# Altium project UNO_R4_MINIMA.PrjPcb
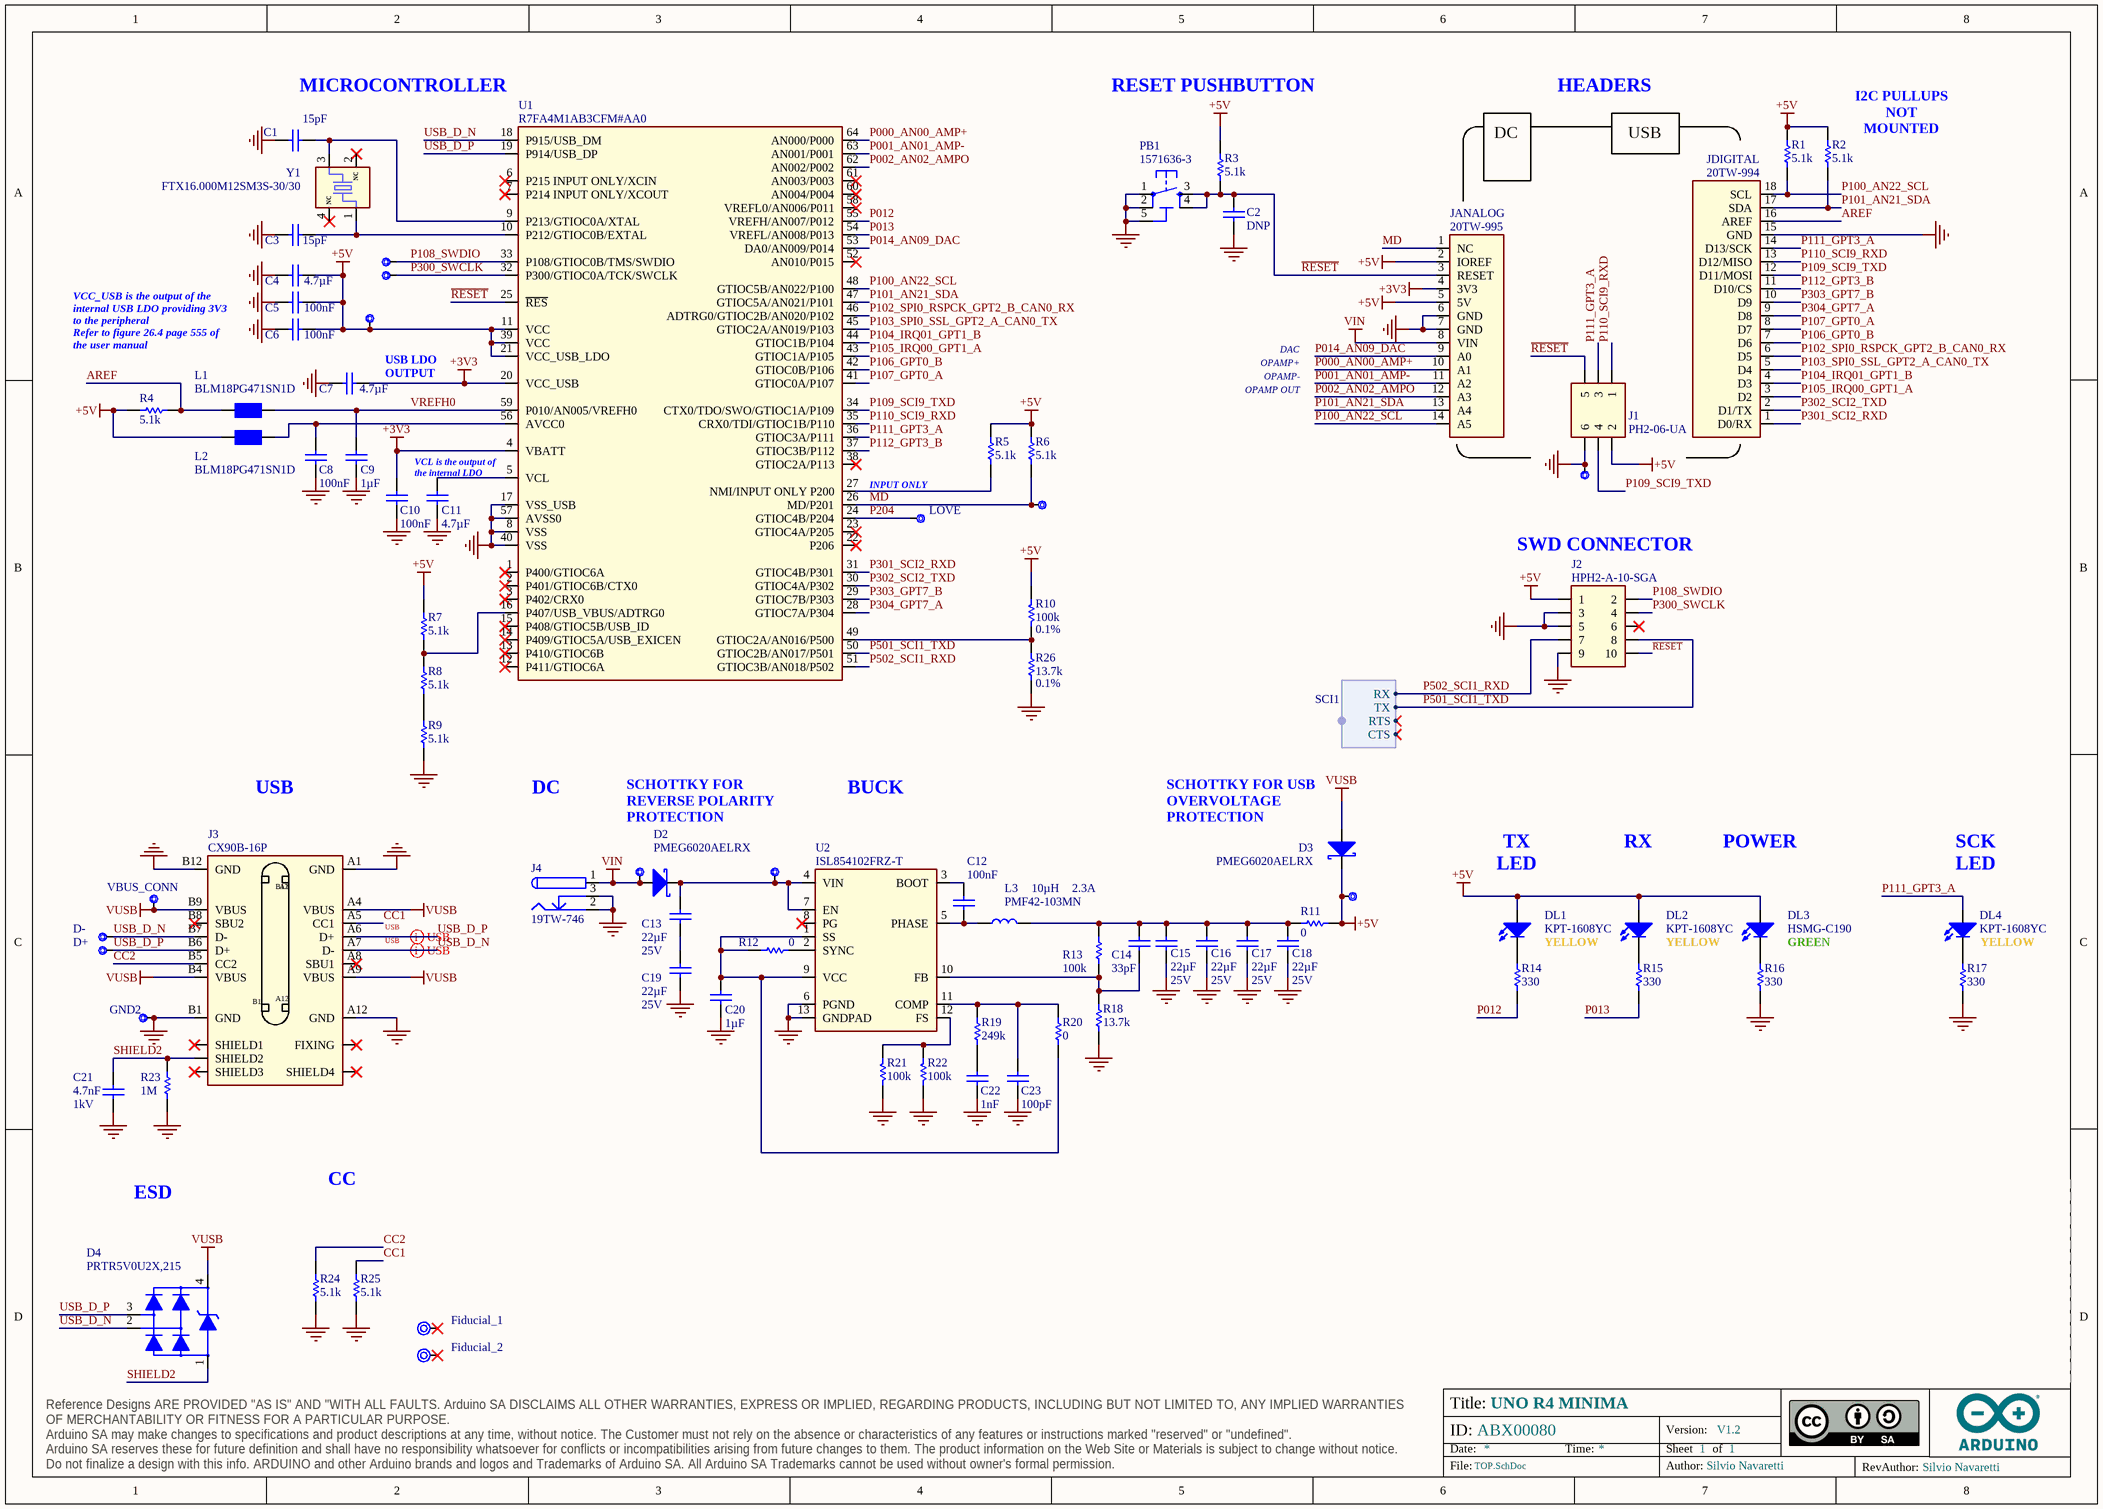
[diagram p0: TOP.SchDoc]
ASSEMBLY_BGA: _; ASSEMBLY_PRESSFIT: _; ASSEMBLY_SMD: X; ASSEMBLY_THT: X; BOARD_INFO_AUTHOR: Silvio Navaretti; BOARD_INFO_Er: _; BOARD_INFO_FLEX: _; BOARD_INFO_FR4: X; BOARD_INFO_FR4_HTG: _; BOARD_INFO_IPC1: _; BOARD_INFO_IPC2: _; BOARD_INFO_IPC3: _; BOARD_INFO_IPC_NA: X; BOARD_INFO_NUMBER_OF_LAYERS: 2; BOARD_INFO_PCB_SIZE: 68.58mm x 53.34mm; BOARD_INFO_POLYMIDE: _; BOARD_INFO_RIGID: X; BOARD_INFO_RIGID/FLEX: _; BOARD_INFO_TBD: _; BOARD_INFO_THICKNESS: 1.6mm; DRILLS_BLIND: _; DRILLS_BURIED: _; DRILLS_COPPER_FILLING: _; DRILLS_FULL: X; DRILLS_LASER: _; DRILLS_PRESSFIT: _; DRILLS_RESIN_FILLING: _; DRILLS_SLOT: _; DRILLS_SOLDER_FILLING: X; FINISH_ADJUSTMENTS: _; FINISH_EDGE_PLATING: _; FINISH_ENIG: _; FINISH_HAL: _; FINISH_HAL_LF: X; FINISH_NI/AU: _; FINISH_SILK_BOTTOM: X; FINISH_SILK_COLOR: WHITE; FINISH_SILK_TOP: X; FINISH_SN/PB: _; FINISH_SOLDERMASK_BOTTOM: X; FINISH_SOLDERMASK_COLOR: BLUE; FINISH_SOLDERMASK_PEELABLE_BOTTOM: _; FINISH_SOLDERMASK_PEELABLE_COLOR: _; FINISH_SOLDERMASK_PEELABLE_TOP: _; FINISH_SOLDERMASK_TOP: X; FINISH_TABS: _; FINISH_TBD: _; INSULATION_MIN_INNER: 0.15mm; INSULATION_MIN_OUTER: 0.15mm; PANEL_MILLING: X; PANEL_NOT_REQUESTED: _; PANEL_NUMBER_OF_FIGURES: 10; PANEL_PROVIDED: X; PANEL_REQUESTED: _; PANEL_SCORING: X; PANEL_SIZE: 284.7mm x 157.16mm; PANEL_TABS: _; SKU: ABX00080; TRACK_MIN_WIDTH_INNER: 0.15mm; TRACK_MIN_WIDTH_OUTER: 0.15mm; Version: V1.2; VIA_1: _; VIA_1_HOLE_MM: _; VIA_1_PAD_MM: _; VIA_2: _; VIA_2_HOLE_MM: _; VIA_2_PAD_MM: _; VIA_3: _; VIA_3_HOLE_MM: _; VIA_3_PAD_MM: _; VIA_4: _; VIA_4_HOLE_MM: _; VIA_4_PAD_MM: _; VIA_5: _; VIA_5_HOLE_MM: _; VIA_5_PAD_MM: _; VIA_THROUGH: X; VIA_THROUGH_HOLE_MM: 0.3; VIA_THROUGH_PAD_MM: 0.6
1 sheet, 84 parts. Net scope: hierarchical (ports join the sheet entries above them; power ports are global).
Board file: PCB.PcbDoc

## Sheet TOP.SchDoc: UNO R4 MINIMA
size A3; Author: Silvio Navaretti; CompanyName: ARDUINO SRL; DrawnBy: Silvio Navaretti; Engineer: Silvio Navaretti; Organization: ARDUINO SRL; Address1: Via Agostino Da Montefeltro 2 Torino TO, Italy; DocumentNumber: ABX00080; Revision: V1.0; SheetNumber: 1; SheetTotal: 1; RevAuthor: Silvio Navaretti

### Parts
1  CMP-018-0004-A.4  [TP-0.8MM]  (value not drawn)  (no BOM)
BUCK_IN_TOP1  CMP-018-0004-A.4  [TP-0.8MM]  (value not drawn)  (no BOM)
C1  value 15pF  [CAP-0402]  (hidden comment: C0402C150J5GACTU)
C2  DNP  [CAP-0402]
C3  value 15pF  [CAP-0402]  (hidden comment: C0402C150J5GACTU)
C4  value 4.7µF  [CAP-0603]  (hidden comment: GRM188R61C475KAAJD)
C5  value 100nF  [CAP-0402]  (hidden comment: GRM155R61H104KE19D)
C6  value 100nF  [CAP-0402]  (hidden comment: GRM155R61H104KE19D)
C7  value 4.7µF  [CAP-0603]  (hidden comment: GRM188R61C475KAAJD)
C8  value 100nF  [CAP-0402]  (hidden comment: GRM155R61H104KE19D)
C9  value 1µF  [CAP-0402]  (hidden comment: CL05A105KP5NNNC)
C10  value 100nF  [CAP-0402]  (hidden comment: GRM155R61H104KE19D)
C11  value 4.7µF  [CAP-0603]  (hidden comment: GRM188R61C475KAAJD)
C12  value 100nF  [CAP-0402]  (hidden comment: GRM155R61H104KE19D)
C13  value 22µF  Voltage: 25V  [CAP-0805]  (hidden comment: CL21A226MAQNNNE)
C14  value 33pF  [CAP-0402]  (hidden comment: GRM1555C1H330JA01D)
C15  value 22µF  Voltage: 25V  [CAP-0805]  (hidden comment: CL21A226MAQNNNE)
C16  value 22µF  Voltage: 25V  [CAP-0805]  (hidden comment: CL21A226MAQNNNE)
C17  value 22µF  Voltage: 25V  [CAP-0805]  (hidden comment: CL21A226MAQNNNE)
C18  value 22µF  Voltage: 25V  [CAP-0805]  (hidden comment: CL21A226MAQNNNE)
C19  value 22µF  Voltage: 25V  [CAP-0805]  (hidden comment: CL21A226MAQNNNE)
C20  value 1µF  [CAP-0402]  (hidden comment: CL05A105KP5NNNC)
C21  value 4.7nF  Voltage: 1kV  [CAP-0805]  (hidden comment: FV21X472K102ECG)
C22  value 1nF  [CAP-0402]  (hidden comment: GRM155R71H102KA01D)
C23  value 100pF  [CAP-0402]  (hidden comment: CC0402JRNPO9BN101)
D2  PMEG6020AELRX  [SOD123-1]
D3  PMEG6020AELRX  [SOD123-1]
D4  PRTR5V0U2X,215  [SOT190P230X110-4N]
D+  CMP-018-0005-A.3  [TP-1.00MM]  (value not drawn)  (no BOM)
D-  CMP-018-0005-A.3  [TP-1.00MM]  (value not drawn)  (no BOM)
DL1  KPT-1608YC  [LEDC1608X80N-AK]
DL2  KPT-1608YC  [LEDC1608X80N-AK]
DL3  HSMG-C190  [LEDC1608X80N-AK]
DL4  KPT-1608YC  [LEDC1608X80N-AK]
Fiducial_1  Fiducial mark 1mm with 2mm solder  [Fiducial mark 1mm with circle-Footprint-1]  (value not drawn)  (no BOM)
Fiducial_2  Fiducial mark 1mm with 2mm solder  [Fiducial mark 1mm with circle-Footprint-1]  (value not drawn)  (no BOM)
GND1  CMP-018-0005-A.3  [TP-1.00MM]  (value not drawn)  (no BOM)
GND2  CMP-018-0005-A.3  [TP-1.00MM]  (value not drawn)  (no BOM)
J1  PH2-06-UA  [2X03]
J2  HPH2-A-10-SGA  [PINHEAD_2X05_127]
J3  CX90B-16P  [CX90B-16P-Footprint-1]
J4  19TW-746  [POWERSUPPLY_DC-21MM]
JANALOG  20TW-995  [1X14-CUSTOM]
JDIGITAL  20TW-994  [1X18-CUSTOM]
L1  BLM18PG471SN1D  [L-0603]
L2  BLM18PG471SN1D  [L-0603]
L3  PMF42-103MN  Max DC Current: 2.3A  Inductance: 10µH  [PMF42]
LOVE  CMP-018-0005-A.3  [TP-1.00MM]  (value not drawn)  (no BOM)
MD  CMP-018-0005-A.3  [TP-1.00MM]  (value not drawn)  (no BOM)
PB1  1571636-3  [TS42]
R1  value 5.1k  [RES-0603]  (hidden comment: CR0603AFX-5101EAS)
R2  value 5.1k  [RES-0603]  (hidden comment: CR0603AFX-5101EAS)
R3  value 5.1k  [RES-0402]  (hidden comment: RC0402FR-075K1L)
R4  value 5.1k  [RES-0402]  (hidden comment: RC0402FR-075K1L)
R5  value 5.1k  [RES-0402]  (hidden comment: RC0402FR-075K1L)
R6  value 5.1k  [RES-0402]  (hidden comment: RC0402FR-075K1L)
R7  value 5.1k  [RES-0402]  (hidden comment: RC0402FR-075K1L)
R8  value 5.1k  [RES-0402]  (hidden comment: RC0402FR-075K1L)
R9  value 5.1k  [RES-0402]  (hidden comment: RC0402FR-075K1L)
R10  value 100k  Tolerance: 0.1%  [RES-0402]  (hidden comment: WF04H1003BT)
R11  value 0  [RES-0402]  (hidden comment: CRCW04020000Z0EDC)
R12  value 0  [RES-0402]  (hidden comment: CRCW04020000Z0EDC)
R13  value 100k  [RES-0402]  (hidden comment: CRCW0402100KFKEDC)
R14  value 330  [RES-0402]  (hidden comment: CRCW0402330RJNED)
R15  value 330  [RES-0402]  (hidden comment: CRCW0402330RJNED)
R16  value 330  [RES-0402]  (hidden comment: CRCW0402330RJNED)
R17  value 330  [RES-0402]  (hidden comment: CRCW0402330RJNED)
R18  value 13.7k  [RES-0402]  (hidden comment: RC0402FR-0713K7L)
R19  value 249k  [RES-0402]  (hidden comment: AC0402FR-07249KL)
R20  value 0  [RES-0402]  (hidden comment: CRCW04020000Z0EDC)
R21  value 100k  [RES-0402]  (hidden comment: CRCW0402100KFKEDC)
R22  value 100k  [RES-0402]  (hidden comment: CRCW0402100KFKEDC)
R23  value 1M  [RES-0402]  (hidden comment: CRCW04021M00FKED)
R24  value 5.1k  [RES-0402]  (hidden comment: RC0402FR-075K1L)
R25  value 5.1k  [RES-0402]  (hidden comment: RC0402FR-075K1L)
R26  value 13.7k  Tolerance: 0.1%  [RES-0402]  (hidden comment: WF04H1372BTL)
SWCLK1  CMP-018-0005-A.3  [TP-1.00MM]  (value not drawn)  (no BOM)
SWDIO1  CMP-018-0005-A.3  [TP-1.00MM]  (value not drawn)  (no BOM)
U1  R7FA4M1AB3CFM#AA0  [CQFP50P1200X1200X170-64L]
U2  ISL854102FRZ-T  [QFN0P300X400X100_HS-13L]
VBUS_CONN  CMP-018-0005-A.3  [TP-1.00MM]  (value not drawn)  (no BOM)
VCC1  CMP-018-0005-A.3  [TP-1.00MM]  (value not drawn)  (no BOM)
VIN_TOP1  CMP-018-0004-A.4  [TP-0.8MM]  (value not drawn)  (no BOM)
Y1  FTX16.000M12SM3S-30/30  [CRYSTAL_3.2x2.5mm_16MHz]

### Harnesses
SCI1: RX, TX, RTS, CTS

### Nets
+3V3: C7.2 C10.2 JANALOG.4(3V3) U1.4(VBATT) U1.20(VCC_USB)
+5V: 1.X C4.2 C5.2 C6.2 D3.C DL1.A DL2.A DL3.A J1.2 J2.1 JANALOG.2(IOREF) JANALOG.5(5V) L2.1 R1.2 R2.2 R3.2 R4.2 R5.1 R6.1 R7.2 R10.2 R11.2 U1.11(VCC) U1.21(VCC_USB_LDO) U1.39(VCC) VCC1.X
GND: C1.2 C2.2 C3.2 C4.1 C5.1 C6.1 C7.1 C8.1 C9.2 C10.1 C11.1 C15.1 C16.1 C17.1 C18.1 C19.1 C20.2 C21.1 C22.1 C23.1 GND1.X GND2.X J1.6 J2.3 J2.5 J2.9 J3.A1(GND) J3.A12(GND) J3.B1(GND) J3.B12(GND) J4.2 J4.3 JANALOG.6(GND) JANALOG.7(GND) JDIGITAL.15(GND) PB1.1 PB1.2 PB1.5(5-GND) R9.1 R16.1 R17.1 R18.1 R21.1 R22.1 R23.1 R24.1 R25.1 R26.1 U1.8(VSS) U1.17(VSS_USB) U1.40(VSS) U1.57(AVSS0) U2.6(PGND) U2.13(GNDPAD)
VIN: D2.A J4.1 JANALOG.8(VIN) VIN_TOP1.X
VUSB: D3.A D4.4 J3.A4(VBUS) J3.A9(VBUS) J3.B4(VBUS) J3.B9(VBUS) VBUS_CONN.X
AREF: JDIGITAL.16(AREF) L1.1 R4.1  [project net AREF_1]
CC1: J3.A5(CC1) R25.2  [project net CC1_1]
CC2: J3.B5(CC2) R24.2  [project net CC2_1]
MD: JANALOG.1(NC) MD.X R6.2 U1.26(MD/P201)  [project net MD_1]
P000_AN00_AMP+: JANALOG.10(A1) U1.64(AN000/P000)  [project net P000_AN00_AMP+_1]
P001_AN01_AMP-: JANALOG.11(A2) U1.63(AN001/P001)  [project net P001_AN01_AMP-_1]
P002_AN02_AMPO: JANALOG.12(A3) U1.62(AN002/P002)  [project net P002_AN02_AMPO_1]
P012: R14.1 U1.55(VREFH/AN007/P012)  [project net P012_1]
P013: R15.1 U1.54(VREFL/AN008/P013)  [project net P013_1]
P014_AN09_DAC: JANALOG.9(A0) U1.53(DA0/AN009/P014)  [project net P014_AN09_DAC_1]
P100_AN22_SCL: JANALOG.14(A5) JDIGITAL.18(SCL) R1.1 U1.48(GTIOC5B/AN022/P100)  [project net P100_AN22_SCL_1]
P101_AN21_SDA: JANALOG.13(A4) JDIGITAL.17(SDA) R2.1 U1.47(GTIOC5A/AN021/P101)  [project net P101_AN21_SDA_1]
P102_SPI0_RSPCK_GPT2_B_CAN0_RX: JDIGITAL.6(D5) U1.46(ADTRG0/GTIOC2B/AN020/P102)  [project net P102_SPI0_RSPCK_GPT2_B_CAN0_RX_1]
P103_SPI0_SSL_GPT2_A_CAN0_TX: JDIGITAL.5(D4) U1.45(GTIOC2A/AN019/P103)  [project net P103_SPI0_SSL_GPT2_A_CAN0_TX_1]
P104_IRQ01_GPT1_B: JDIGITAL.4(D3) U1.44(GTIOC1B/P104)  [project net P104_IRQ01_GPT1_B_1]
P105_IRQ00_GPT1_A: JDIGITAL.3(D2) U1.43(GTIOC1A/P105)  [project net P105_IRQ00_GPT1_A_1]
P106_GPT0_B: JDIGITAL.7(D6) U1.42(GTIOC0B/P106)  [project net P106_GPT0_B_1]
P107_GPT0_A: JDIGITAL.8(D7) U1.41(GTIOC0A/P107)  [project net P107_GPT0_A_1]
P108_SWDIO: J2.2 SWDIO1.X U1.33(P108/GTIOC0B/TMS/SWDIO)  [project net P108_SWDIO_1]
P109_SCI9_TXD: J1.4 JDIGITAL.12(D11/MOSI) U1.34(CTX0/TDO/SWO/GTIOC1A/P109)  [project net P109_SCI9_TXD_1]
P110_SCI9_RXD: J1.1 JDIGITAL.13(D12/MISO) U1.35(CRX0/TDI/GTIOC1B/P110)  [project net P110_SCI9_RXD_1]
P111_GPT3_A: DL4.A J1.3 JDIGITAL.14(D13/SCK) U1.36(GTIOC3A/P111)  [project net P111_GPT3_A_1]
P112_GPT3_B: JDIGITAL.11(D10/CS) U1.37(GTIOC3B/P112)  [project net P112_GPT3_B_1]
P204: LOVE.X U1.24(GTIOC4B/P204)  [project net P204_1]
P300_SWCLK: J2.4 SWCLK1.X U1.32(P300/GTIOC0A/TCK/SWCLK)  [project net P300_SWCLK_1]
P301_SCI2_RXD: JDIGITAL.1(D0/RX) U1.31(GTIOC4B/P301)  [project net P301_SCI2_RXD_1]
P302_SCI2_TXD: JDIGITAL.2(D1/TX) U1.30(GTIOC4A/P302)  [project net P302_SCI2_TXD_1]
P303_GPT7_B: JDIGITAL.10(D9) U1.29(GTIOC7B/P303)  [project net P303_GPT7_B_1]
P304_GPT7_A: JDIGITAL.9(D8) U1.28(GTIOC7A/P304)  [project net P304_GPT7_A_1]
P501_SCI1_TXD: J2.8 U1.50(GTIOC2B/AN017/P501) ; harness SCI1.TX
P502_SCI1_RXD: J2.7 U1.51(GTIOC3B/AN018/P502) ; harness SCI1.RX
~{RESET}: C2.1 J1.5 J2.10 JANALOG.3(RESET) PB1.3 PB1.4 R3.1 U1.25(~{RES})  [project net ~{RESET}_1]
SHIELD2: C21.2 D4.1 J3.SHIELD2 R23.2  [project net SHIELD2_1]
USB_D_N: D4.2 D-.X J3.A7(D-) J3.B7(D-) U1.18(P915/USB_DM)  [project net USB_D_N_1]
USB_D_P: D4.3 D+.X J3.A6(D+) J3.B6(D+) U1.19(P914/USB_DP)  [project net USB_D_P_1]
VREFH0: C9.1 L1.2 U1.59(P010/AN005/VREFH0)  [project net VREFH0_1]
NetBUCK_IN_TOP1_X: BUCK_IN_TOP1.X C13.2 D2.C U2.4(VIN) U2.7(EN)
NetC1_1: C1.1 U1.9(P213/GTIOC0A/XTAL) Y1.3
NetC3_1: C3.1 U1.10(P212/GTIOC0B/EXTAL) Y1.1
NetC8_2: C8.2 L2.2 U1.56(AVCC0)
NetC11_2: C11.2 U1.5(VCL)
NetC12_1: C12.1 L3.1 U2.5(PHASE)
NetC12_2: C12.2 U2.3(BOOT)
NetC13_1: C13.1 C19.2
NetC14_1: C14.1 R13.2 R18.2 U2.10(FB)
NetC14_2: C14.2 C15.2 C16.2 C17.2 C18.2 L3.2 R11.1 R13.1
NetC20_1: C20.1 R12.2 R20.2 U2.1(SS) U2.9(VCC)
NetC22_2: C22.2 R19.1
NetC23_2: C23.2 R19.2 R20.1 U2.11(COMP)
NetDL1_C: DL1.C R14.2
NetDL2_C: DL2.C R15.2
NetDL3_C: DL3.C R16.2
NetDL4_C: DL4.C R17.2
NetR5_2: R5.2 U1.27(NMI/INPUT_ONLY_P200)
NetR7_1: R7.1 R8.2 U1.16(P407/USB_VBUS/ADTRG0)
NetR8_1: R8.1 R9.2
NetR10_1: R10.1 R26.2 U1.49(GTIOC2A/AN016/P500)
NetR12_1: R12.1 U2.2(SYNC)
NetR21_2: R21.2 R22.2 U2.12(FS)

Not connected (* = marked no-connect by the designer): Fiducial_1 1*; Fiducial_2 1*; J2 6*; J3 A8(SBU1)* B8(SBU2)* FIXING* SHIELD1* SHIELD3* SHIELD4*; U1 1(P400/GTIOC6A)* 2(P401/GTIOC6B/CTX0)* 3(P402/CRX0)* 6(P215_INPUT_ONLY/XCIN)* 7(P214_INPUT_ONLY/XCOUT)* 12(P411/GTIOC6A)* 13(P410/GTIOC6B)* 14(P409/GTIOC5A/USB_EXICEN)* 15(P408/GTIOC5B/USB_ID)* 22(P206)* 23(GTIOC4A/P205)* 38(GTIOC2A/P113)* 52(AN010/P015)* 58(VREFL0/AN006/P011)* 60(AN004/P004)* 61(AN003/P003)*; U2 8(PG)*; Y1 2(NC)* 4(NC)*

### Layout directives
differential pair; differential pair class USB: USB_D_N_1, USB_D_P_1

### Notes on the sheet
- MICROCONTROLLER
- RESET PUSHBUTTON
- HEADERS
- DC
- USB
- (near R2) I2C PULLUPS
  NOT MOUNTED
- VCC_USB is the output of the internal USB LDO providing 3V3 to the peripheral
  Refer to figure 26.4 page 555 of the user manual
- USB LDO OUTPUT
- DAC
- OPAMP+
- OPAMP-
- OPAMP OUT
- VCL is the output of the internal LDO
- INPUT ONLY
- SWD CONNECTOR
- USB CONNECTOR
- DC JACK
- SCHOTTKY FOR REVERSE POLARITY PROTECTION
- BUCK CONVERTER
- (near D3) SCHOTTKY FOR USB OVERVOLTAGE PROTECTION
- (near DL1) TX
  LED
- RX
  LED
- POWER LED
- (near DL4) SCK LED
- YELLOW
- GREEN
- ESD
  PROTECTION
- CC RESISTORS

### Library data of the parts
1 BUCK_IN_TOP1 VIN_TOP1 = UT0012-A.4: Test point 0.8mm
C1 C3 = C0025-A.16: CAP CHIP 0402 15pF 5% 50V C0G; Manufacturer: KEMET; Code Arduino: A5498
C2 = UT0021-A.3
C4 C7 C11 = C0054-A.16: CAP CHIP 0603 4.7uF 10% 16V X5R; Manufacturer: Murata; Code Arduino: A5072
C5 C6 C8 C10 C12 = C0015-A.14: CAP CHIP 0402 100nF 10% 50V X5R; Manufacturer: Murata; Code Arduino: A5141
C9 C20 = C0017-A.14: CAP CHIP 0402 1uF 10% 10V X5R; Manufacturer: Samsung Electro-Mechanics; Code Arduino: 0133
C13 C15-C19 = C0111-A.7: CAP CHIP 0805 22uF 20% 25V X5R; Manufacturer: Samsung Electro-Mechanics; Code Arduino: C0111
C14 = C0034-A.14: CAP CHIP 0402 33pF 5% 50V C0G; Manufacturer: Murata; Code Arduino: A5494
C21 = C0059-A.14: CAP CHIP 0805 4.7nF 10% 1000V X7R; Manufacturer: PSA Shenzen; Code Arduino: 0689
C22 = C0007-A.15: CAP CHIP 0402 1nF 10% 50V X7R; Manufacturer: KEMET; Code Arduino: 2321
C23 = C0013-A.4: CAP CHIP 0402 100pF 10% 50V C0G; Manufacturer: Yageo; Code Arduino: C0013; Tolerance: 5%
D2 D3 = D0026-A.6: DIODE SCHOTTKY SMD 2A 60V SOD123FL; Manufacturer: Nexperia; Manucturer Part Number 2: SS26L; Code Arduino: 2208; Forward Voltage: 0.6V; Manucturer 2: Hottech
D4 = D0025-A.5: TVS ARRAY 4LIN.8kV 1pF SOT143B; Manufacturer: Nexperia; Device Type: ESD protection; Code Arduino: 2209
D+ D- GND1 GND2 LOVE MD SWCLK1 SWDIO1 VBUS_CONN VCC1 = UT0013-A.4: Test point 1.00mm
DL1 DL2 DL4 = L0008-A.5: LED SMD 0603 GIA588   8mcd 120^; Manufacturer: Kingbright; Code Arduino: 2243
DL3 = L0009-A.5: LED SMD 0603 GREEN/568 15mcd 120^; Manufacturer: Broadcom; Code Arduino: 2204
Fiducial_1 Fiducial_2 = UT0024-A.6
J1 = J0004-A.5: CONN Header Through Hole 6 position 0.100" (2.54mm); Manufacturer: Adam Tech; Code Arduino: 0114
J2 = J0068-A.9: CONN CONN STRIP THD 1,27 M/2/D 10v AuF H6,3 JTAG; Manufacturer: Adam Tech; Code Arduino: 0171
J3 = J0272-A.3: CONN RCPT USB3.1 TYPEC 16POS SMD; Manufacturer: Hirose; Code Arduino: J0272
J4 = J0236-A.5: CONN PWR JACK 2.1X5.5MM SOLDER; Manufacturer: 4UCON; Code Arduino: 0018
JANALOG = J0063-A.7: CONN STRIP F/1/D 14v SER.NERA s1pin; Manufacturer: 4UCONN; Code Arduino: 3649
JDIGITAL = J0035-A.10: CONN STRIP F/1/D 18v SER.NERA s1pin; Manufacturer: 4UCONN; Code Arduino: 3648
L1 L2 = I0006-A.5: FERRITE SMD 0603 470R 1A 0.2R; Manufacturer: Murata; Test Frequency: 100MHz; Code Arduino: 2200; Tolerance: 25%; DC Resistance (DCR): 200mR
L3 = I0072-A.3: IND 10uH 20%, max 235mR, IDC 2.3A, Isat 2.3A, shielded, max 5MHz, 4.5x4.5x1.8mm; Manufacturer: K-WELL; DC Resistance (DCR): 235m; Code Arduino: I0072
PB1 = B0005-A.8: PUSHBUTTON SMD 6x6 5 PINS; Manufacturer: TE Connectivity; Code Arduino: 0946
R1 R2 = R0239-A.11: RES CHIP 0603 5k1 1% 1/10W; Manufacturer: Bourns; Power: 100mW; Code Arduino: R0239; Temperature coefficient: 100ppm
R3 R7-R9 R24 R25 = R0210-A.18: RES CHIP 0402 5k1 1% 1/16W; Manufacturer: YAGEO; Code Arduino: R0210; Power: 63mW; Temperature coefficient: 100ppm
R4-R6 = R0210-A.18: RES CHIP 0402 5k1 1% 1/16W; Manufacturer: YAGEO; Power: 63mW; Code Arduino: R0210; Temperature coefficient: 100ppm
R10 = R0247-A.4: RES CHIP 0402 100k 0.1% 100ppm 1/16W; Manufacturer: Walsin; Code Arduino: R0247; Power: 62.5mW
R11 R12 R20 = R0000-A.23: RES CHIP 0402 0R 1/16W; Manufacturer: Vishay; Code Arduino: 0039; Power: 62.5mW; Tolerance: 0%; Temperature coefficient: 0ppm
R13 = R0001-A.23: RES CHIP 0402 100k 1% 1/16W; Manufacturer: Vishay; Power: 62.5mW; Code Arduino: 0134; Temperature coefficient: 100ppm
R14-R17 = R0017-A.23: RES CHIP 0402 330R 5% 1/16W; Manufacturer: Vishay; Code Arduino: 2229; Power: 62.5mW; Temperature coefficient: 200ppm
R18 = R0233-A.9: RES CHIP 0402 13k7 1% 1/16W; Manufacturer: YAGEO; Power: 62.5mW; Code Arduino: R0233; Temperature coefficient: 100ppm
R19 = R0234-A.8: RES CHIP 0402 249k 1% 1/16W; Manufacturer: YAGEO; Code Arduino: R0234; Power: 62.5mW; Temperature coefficient: 100ppm
R21 R22 = R0001-A.23: RES CHIP 0402 100k 1% 1/16W; Manufacturer: Vishay; Code Arduino: 0134; Power: 62.5mW; Temperature coefficient: 100ppm
R23 = R0058-A.23: RES CHIP 0402 1M 1% 1/16W; Manufacturer: Vishay; Power: 62.5mW; Code Arduino: 0139; Temperature coefficient: 100ppm
R26 = R0248-A.3: RES CHIP 0402 13k7 0.1% 100PPM 1/16W; Manufacturer: Walsin; Power: 62.5mW; Code Arduino: R0248; Temperature coefficient: 200ppm
U1 = U0274-A.7: IC uC RA4M1 32b M4 48MHz 254KB flash 32KB RAM 105°C LQFP64 10x10mm; Manufacturer: Renesas; Code Arduino: U0274
U2 = U0275-A.5: IC BUCK Vin 40V Iout 1.2A 2MHz 12DFN 3x4mm; Manufacturer: Renesas; Code Arduino: U0275
Y1 = X0019-A.12: CRYSTAL 16.0000MHz 12pF SMD; Manufacturer: Fronter Electronics; Code Arduino: 0395; Frequency: 16MHz

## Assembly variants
ABX00080: not fitted C1 C2 C3 C22 C23 R1 R2 R12 R19 Y1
